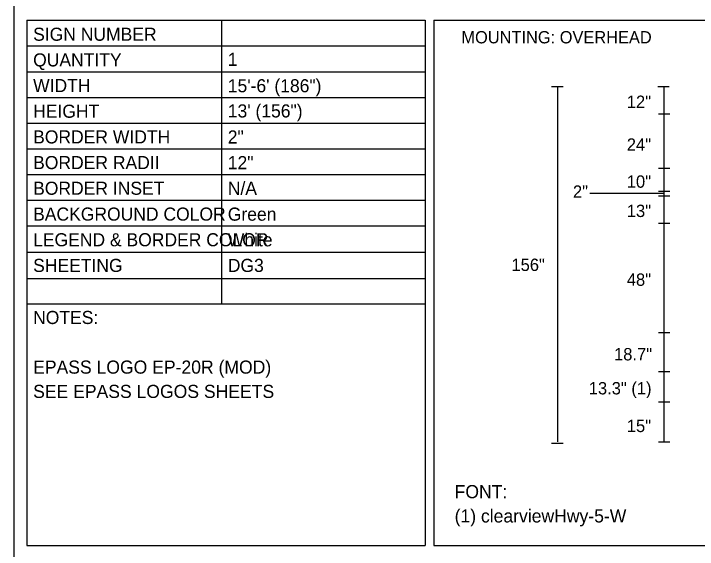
# Model space of a CAD drawing. Extents: x 10268312 to 10268472, y 2142583 to 2142688.
# Drawn here: x 10268394.73 to 10268433.77, y 2142609.32 to 2142639.91 of the extents above; entities that cross this region are included whole.
import ezdxf

# ---------------------------------------------------------------- set-up
doc = ezdxf.new("R2010")
doc.units = 0
for name, color, linetype in [('GSDims', 7, 'Continuous'), ('SheetBorder_dp', 7, 'Continuous'), ('SumBoxLines_dp', 7, 'Continuous'), ('TextMisc', 7, 'Continuous')]:
    doc.layers.add(name, color=color, linetype=linetype)

msp = doc.modelspace()

# ---------------------------------------------------------------- linework, layer by layer
at = {"layer": 'GSDims'}
for p, q in [((10268425.454, 2142635.752), (10268426.115, 2142635.752)), ((10268425.802, 2142615.451), (10268425.803, 2142635.752)), ((10268431.511, 2142635.752), (10268432.172, 2142635.752)), ((10268431.88, 2142615.451), (10268431.88, 2142635.752)), ((10268431.55, 2142634.196), (10268432.211, 2142634.196)), ((10268431.55, 2142634.196), (10268432.211, 2142634.196)), ((10268431.55, 2142631.084), (10268432.211, 2142631.084)), ((10268427.627, 2142629.648), (10268431.88, 2142629.648)), ((10268431.55, 2142629.768), (10268432.211, 2142629.768)), ((10268431.55, 2142629.504), (10268432.211, 2142629.504)), ((10268431.55, 2142627.942), (10268432.211, 2142627.942)), ((10268431.55, 2142621.694), (10268432.211, 2142621.694)), ((10268431.55, 2142619.469), (10268432.211, 2142619.469)), ((10268431.55, 2142617.737), (10268432.211, 2142617.737)), ((10268431.549, 2142615.451), (10268432.211, 2142615.451)), ((10268425.454, 2142615.38), (10268426.115, 2142615.38))]:
    msp.add_line(p, q, dxfattribs=at)
at = {"layer": 'SheetBorder_dp'}
msp.add_line((10268394.73, 2142688.282), (10268394.73, 2142592.282), dxfattribs=at)
at = {"layer": 'SumBoxLines_dp'}
for p, q in [((10268395.48, 2142639.532), (10268418.23, 2142639.532)), ((10268395.48, 2142639.532), (10268395.48, 2142609.532)), ((10268406.598, 2142639.528), (10268406.598, 2142623.345)), ((10268418.23, 2142639.532), (10268418.23, 2142609.532)), ((10268418.73, 2142639.532), (10268470.98, 2142639.532)), ((10268418.73, 2142639.532), (10268418.73, 2142609.532)), ((10268395.48, 2142638.066), (10268418.23, 2142638.066)), ((10268395.48, 2142636.591), (10268418.23, 2142636.591)), ((10268395.48, 2142635.125), (10268418.23, 2142635.125)), ((10268395.48, 2142633.659), (10268418.23, 2142633.659)), ((10268395.48, 2142632.193), (10268418.23, 2142632.193)), ((10268395.48, 2142630.727), (10268418.23, 2142630.727)), ((10268395.48, 2142629.262), (10268418.23, 2142629.262)), ((10268395.48, 2142627.786), (10268418.23, 2142627.786)), ((10268395.48, 2142626.281), (10268418.23, 2142626.281)), ((10268395.48, 2142624.776), (10268418.23, 2142624.776)), ((10268395.478, 2142623.345), (10268418.229, 2142623.345)), ((10268395.48, 2142609.532), (10268418.23, 2142609.532)), ((10268418.73, 2142609.532), (10268470.98, 2142609.532))]:
    msp.add_line(p, q, dxfattribs=at)

# ---------------------------------------------------------------- texts
at = {"layer": 'GSDims'}
for s, height, p in [('MOUNTING: OVERHEAD ', 0.7, (10268420.3, 2142638.211)), ('24"', 0.7056, (10268429.746, 2142632.081)), ('10"', 0.7056, (10268429.746, 2142629.967)), ('2"', 0.7056, (10268426.67, 2142629.393)), ('13"', 0.7056, (10268429.746, 2142628.294)), ('156"', 0.7056, (10268423.159, 2142625.213)), ('48"', 0.7056, (10268429.746, 2142624.365)), ('18.7"', 0.7056, (10268429.017, 2142620.107)), ('13.3" (1)', 0.7056, (10268427.574, 2142618.164)), ('15"', 0.7056, (10268429.746, 2142616.013))]:
    msp.add_text(s, height=height, dxfattribs=at).set_placement(p)
msp.add_text('12"', height=0.7056, rotation=359.998, dxfattribs=at).set_placement((10268429.746, 2142634.524))
at = {"layer": 'TextMisc'}
for s, height, p in [('SIGN NUMBER', 0.74756, (10268395.841, 2142638.359)), ('QUANTITY', 0.7476, (10268395.841, 2142636.893)), ('1', 0.748, (10268406.959, 2142636.926)), ('WIDTH', 0.7476, (10268395.841, 2142635.428)), ('15\'-6\' (186")', 0.74756, (10268406.959, 2142635.418)), ('HEIGHT', 0.7476, (10268395.841, 2142633.962)), ('13\' (156")', 0.7476, (10268406.959, 2142633.98)), ('BORDER WIDTH', 0.74756, (10268395.841, 2142632.496)), ('2"', 0.7476, (10268406.959, 2142632.492)), ('BORDER RADII', 0.74756, (10268395.841, 2142631.03)), ('12"', 0.7476, (10268406.959, 2142631.027)), ('BORDER INSET', 0.74756, (10268395.841, 2142629.564)), ('N/A', 0.7476, (10268406.959, 2142629.561)), ('BACKGROUND COLOR', 0.74756, (10268395.841, 2142628.089)), ('Green', 0.7476, (10268406.959, 2142628.085)), ('LEGEND & BORDER COLOR', 0.74756, (10268395.841, 2142626.623)), ('White', 0.7476, (10268406.959, 2142626.619)), ('SHEETING', 0.7476, (10268395.841, 2142625.157)), ('DG3', 0.7476, (10268406.959, 2142625.157)), ('NOTES:', 0.7476, (10268395.84, 2142622.184)), ('EPASS LOGO EP-20R (MOD)', 0.75, (10268395.84, 2142619.349)), ('SEE EPASS LOGOS SHEETS', 0.75, (10268395.84, 2142617.961)), ('FONT:', 0.75, (10268419.914, 2142612.238)), ('(1) clearviewHwy-5-W', 0.75, (10268419.914, 2142610.85))]:
    msp.add_text(s, height=height, dxfattribs=at).set_placement(p)

doc.saveas('drawing.dxf')
